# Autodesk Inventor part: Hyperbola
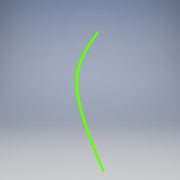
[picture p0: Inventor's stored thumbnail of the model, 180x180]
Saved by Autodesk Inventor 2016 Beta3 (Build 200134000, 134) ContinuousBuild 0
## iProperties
Created: 2008-02
Part Number: Hyperbola
Document SubType Name: Modeling
Designer: Autodesk, Inc.
Density: 1 g/cm^3
Material: Generic
Appearance: Default
Author: Autodesk, Inc.
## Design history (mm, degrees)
sketch "Sketch1"
  geometry: 300 further points
  constraints: 300 other
